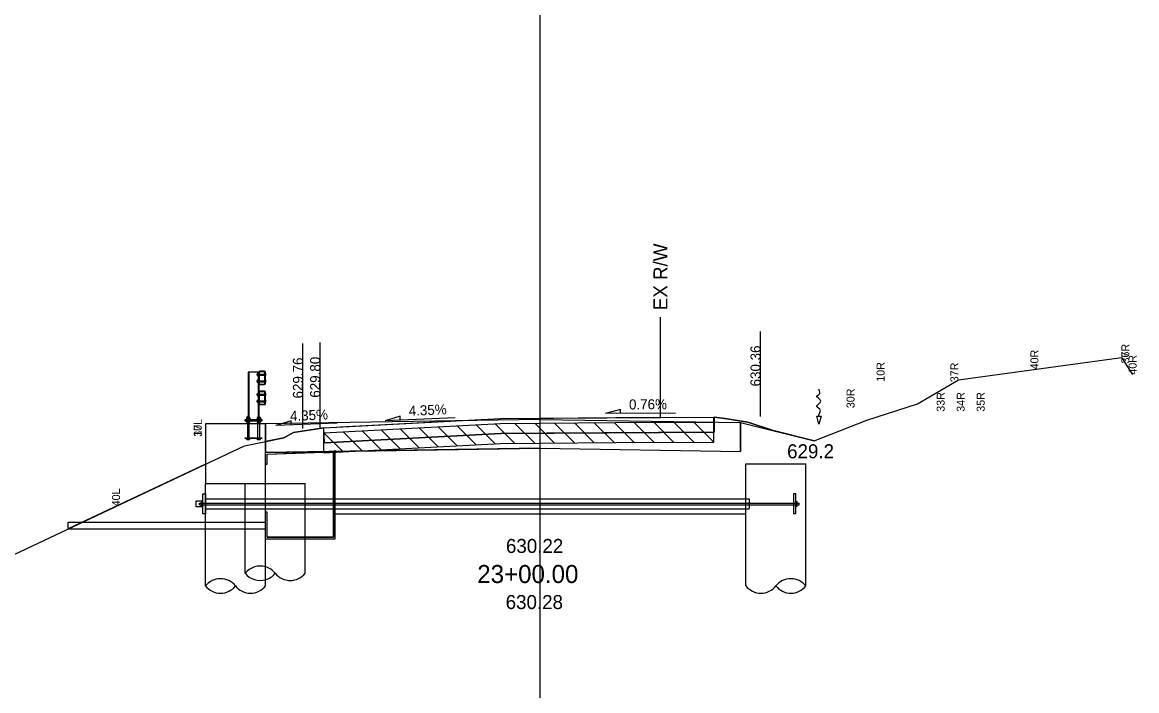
# Model space of a CAD drawing. Extents: x 1866342 to 1870084, y 421982 to 426629.
# Drawn here: x 1866442.2 to 1866497.9, y 422514.3 to 422547.7 of the extents above; entities that cross this region are included whole.
import ezdxf

# ---------------------------------------------------------------- set-up
doc = ezdxf.new("R2010")
doc.units = 0
for name, color, linetype in [('BR_P_Det_Object', 7, 'Continuous'), ('BR_P_Drain_Object', 7, 'Continuous'), ('BR_P_Gen_Hatch', 7, 'Continuous'), ('BR_P_Gen_Porous_Backfill', 7, 'Continuous'), ('BR_P_Sub_Deep_Hidden', 7, 'Continuous'), ('BR_P_Sub_Deep_Object', 7, 'Continuous'), ('BR_P_Sub_Object', 7, 'Continuous'), ('DR_P_Flow_Arrow', 7, 'Continuous'), ('GK_Cells', 7, 'Continuous'), ('RW_X_Fee_RW', 7, 'Continuous'), ('ST_Details', 7, 'Continuous'), ('XS_P_Annotation', 7, 'Continuous'), ('XS_P_Earthwork_Shapes', 7, 'Continuous'), ('XS_P_Finished_Grade', 7, 'Continuous'), ('XS_P_Pavt_Surface', 7, 'Continuous'), ('XS_P_Subgrade', 7, 'Continuous'), ('XS_P_Text_Info', 7, 'Continuous'), ('XS_P_Text_MarkedPoint', 7, 'Continuous'), ('XS_X_Ground_Line', 7, 'Continuous'), ('XS_X_Pavt', 7, 'Continuous')]:
    doc.layers.add(name, color=color, linetype=linetype)

msp = doc.modelspace()

# ---------------------------------------------------------------- linework, layer by layer
at = {"layer": 'BR_P_Det_Object'}
for p, q in [((1866451.264, 422523.135), (1866451.264, 422524.135)), ((1866451.264, 422524.135), (1866451.389, 422524.135)), ((1866451.389, 422524.135), (1866451.389, 422523.135)), ((1866451.389, 422523.885), (1866454.389, 422523.885)), ((1866480.764, 422524.135), (1866480.764, 422523.135)), ((1866480.889, 422524.135), (1866480.764, 422524.135)), ((1866480.889, 422523.135), (1866480.889, 422524.135)), ((1866450.93, 422523.484), (1866450.93, 422523.783)), ((1866450.93, 422523.783), (1866451.264, 422523.783)), ((1866451.264, 422523.484), (1866450.93, 422523.484)), ((1866451.097, 422523.676), (1866481.055, 422523.676)), ((1866451.097, 422523.593), (1866451.097, 422523.676)), ((1866451.097, 422523.593), (1866481.055, 422523.593)), ((1866451.264, 422523.729), (1866451.2, 422523.729)), ((1866451.2, 422523.54), (1866451.2, 422523.729)), ((1866451.264, 422523.54), (1866451.2, 422523.54)), ((1866451.389, 422523.385), (1866454.389, 422523.385)), ((1866480.889, 422523.75), (1866480.952, 422523.75)), ((1866480.889, 422523.52), (1866480.952, 422523.52)), ((1866480.952, 422523.52), (1866480.952, 422523.75)), ((1866481.055, 422523.593), (1866481.055, 422523.676)), ((1866451.389, 422523.135), (1866451.264, 422523.135)), ((1866480.889, 422523.135), (1866480.764, 422523.135))]:
    msp.add_line(p, q, dxfattribs=at)
at = {"layer": 'BR_P_Drain_Object'}
for p, q in [((1866454.389, 422523.885), (1866478.555, 422523.885)), ((1866478.555, 422523.885), (1866478.555, 422523.385)), ((1866454.389, 422523.385), (1866478.555, 422523.385)), ((1866444.524, 422522.718), (1866454.389, 422522.718)), ((1866444.524, 422522.385), (1866444.524, 422522.718)), ((1866444.524, 422522.385), (1866454.389, 422522.385))]:
    msp.add_line(p, q, dxfattribs=at)
at = {"layer": 'BR_P_Gen_Hatch'}
msp.add_lwpolyline([(1866454.389, 422525.617), (1866454.472, 422525.617), (1866454.472, 422526.117), (1866457.789, 422526.24), (1866457.789, 422521.968), (1866454.472, 422521.968), (1866454.472, 422523.218), (1866454.389, 422523.218)], close=True, dxfattribs=at)
at = {"layer": 'BR_P_Gen_Porous_Backfill'}
for p, q in [((1866454.472, 422526.117), (1866457.389, 422526.234)), ((1866454.472, 422525.617), (1866454.472, 422526.117)), ((1866457.789, 422526.24), (1866457.389, 422526.234)), ((1866457.789, 422521.968), (1866457.789, 422526.24)), ((1866454.472, 422525.617), (1866454.389, 422525.617)), ((1866454.472, 422523.218), (1866454.389, 422523.218)), ((1866454.472, 422521.968), (1866454.472, 422523.218)), ((1866454.472, 422521.968), (1866457.789, 422521.968))]:
    msp.add_line(p, q, dxfattribs=at)
at = {"layer": 'BR_P_Sub_Deep_Hidden'}
msp.add_line((1866456.373, 422524.635), (1866454.389, 422524.635), dxfattribs=at)
for points in [[(1866453.373, 422520.171), (1866453.373, 422524.635)], [(1866456.373, 422521.885), (1866456.373, 422524.635)]]:
    msp.add_lwpolyline(points, dxfattribs=at)
for centre, major_axis, start_param, end_param in [((1866454.123, 422519.568), (0.908, 0.32), 0.952163, 2.125879), ((1866454.123, 422520.774), (0.908, -0.32), 4.157306, 5.331022)]:
    msp.add_ellipse(centre, major_axis=major_axis, ratio=0.999997, start_param=start_param, end_param=end_param, dxfattribs=at)
at = {"layer": 'BR_P_Sub_Deep_Object'}
msp.add_line((1866478.389, 422525.635), (1866481.389, 422525.635), dxfattribs=at)
for points in [[(1866478.389, 422519.538), (1866478.389, 422525.635)], [(1866481.389, 422519.538), (1866481.389, 422525.635)], [(1866451.389, 422519.538), (1866451.389, 422524.635)], [(1866454.389, 422519.538), (1866454.389, 422524.635)], [(1866456.373, 422520.171), (1866456.373, 422521.885)]]:
    msp.add_lwpolyline(points, dxfattribs=at)
for centre, major_axis, start_param, end_param in [((1866454.123, 422519.568), (0.908, 0.32), 0.338571, 0.952163), ((1866454.123, 422520.774), (0.908, -0.32), 5.331022, 5.944615), ((1866455.623, 422520.774), (0.908, 0.32), 3.480163, 5.267472), ((1866452.139, 422518.935), (0.908, 0.32), 0.338571, 2.125879), ((1866452.139, 422520.141), (0.908, -0.32), 4.157306, 5.944615), ((1866453.639, 422520.141), (0.908, 0.32), 3.480163, 5.267472), ((1866479.139, 422520.141), (-0.908, 0.32), 1.015713, 2.803022), ((1866480.639, 422518.935), (-0.908, 0.32), 4.157306, 5.944615), ((1866480.639, 422520.141), (-0.908, -0.32), 0.33857, 2.125879)]:
    msp.add_ellipse(centre, major_axis=major_axis, ratio=0.999997, start_param=start_param, end_param=end_param, dxfattribs=at)
at = {"layer": 'BR_P_Sub_Object'}
for p, q in [((1866454.389, 422527.635), (1866451.389, 422527.635)), ((1866451.389, 422527.635), (1866451.389, 422524.635)), ((1866454.389, 422524.635), (1866454.389, 422527.635))]:
    msp.add_line(p, q, dxfattribs=at)
msp.add_lwpolyline([(1866454.389, 422524.635), (1866451.389, 422524.635)], dxfattribs=at)
at = {"layer": 'DR_P_Flow_Arrow'}
for p, q in [((1866482.037, 422527.616), (1866481.93, 422528.016)), ((1866481.93, 422528.016), (1866482.145, 422528.016)), ((1866482.145, 422528.016), (1866482.037, 422527.616))]:
    msp.add_line(p, q, dxfattribs=at)
msp.add_spline([(1866482.038, 422528.016), (1866482.038, 422528.032), (1866482.076, 422528.196), (1866482.112, 422528.301), (1866481.928, 422528.513), (1866482.135, 422528.755), (1866481.928, 422529.035), (1866482.04, 422529.092), (1866482.037, 422529.366)], degree=3, dxfattribs=at)
at = {"layer": 'GK_Cells'}
msp.add_line((1866468.119, 422490.634), (1866468.119, 422611.57), dxfattribs=at)
at = {"layer": 'RW_X_Fee_RW'}
msp.add_line((1866474.119, 422527.954), (1866474.119, 422532.954), dxfattribs=at)
at = {"layer": 'ST_Details'}
for p, q in [((1866453.524, 422530.218), (1866453.524, 422528)), ((1866454.055, 422530.218), (1866453.524, 422530.218)), ((1866453.562, 422530.218), (1866453.562, 422527.993)), ((1866453.971, 422530.119), (1866453.955, 422530.119)), ((1866453.955, 422530.119), (1866453.955, 422530.067)), ((1866453.971, 422530.067), (1866453.955, 422530.067)), ((1866453.971, 422530.126), (1866453.971, 422530.06)), ((1866453.98, 422530.071), (1866454.017, 422530.071)), ((1866454.017, 422530.137), (1866453.981, 422530.137)), ((1866453.981, 422530.115), (1866454.017, 422530.115)), ((1866453.981, 422530.049), (1866454.017, 422530.049)), ((1866454.017, 422530.218), (1866454.017, 422527.993)), ((1866454.017, 422530.049), (1866454.017, 422530.137)), ((1866454.055, 422530.218), (1866454.055, 422528)), ((1866454.055, 422530.208), (1866454.055, 422529.645)), ((1866454.081, 422530.208), (1866454.081, 422529.645)), ((1866454.081, 422530.119), (1866454.363, 422530.119)), ((1866454.081, 422530.067), (1866454.363, 422530.067)), ((1866454.337, 422530.26), (1866454.107, 422530.26)), ((1866454.337, 422530.234), (1866454.107, 422530.234)), ((1866454.363, 422529.645), (1866454.363, 422530.208)), ((1866454.389, 422529.645), (1866454.389, 422530.208)), ((1866453.971, 422529.786), (1866453.955, 422529.786)), ((1866453.955, 422529.786), (1866453.955, 422529.734)), ((1866453.971, 422529.734), (1866453.955, 422529.734)), ((1866453.971, 422529.793), (1866453.971, 422529.726)), ((1866453.98, 422529.738), (1866454.017, 422529.738)), ((1866454.017, 422529.804), (1866453.981, 422529.804)), ((1866453.981, 422529.782), (1866454.017, 422529.782)), ((1866453.981, 422529.715), (1866454.017, 422529.715)), ((1866454.017, 422529.715), (1866454.017, 422529.804)), ((1866454.081, 422529.786), (1866454.363, 422529.786)), ((1866454.081, 422529.734), (1866454.363, 422529.734)), ((1866454.107, 422529.619), (1866454.337, 422529.619)), ((1866454.107, 422529.593), (1866454.337, 422529.593)), ((1866453.971, 422529.119), (1866453.955, 422529.119)), ((1866453.955, 422529.119), (1866453.955, 422529.067)), ((1866453.971, 422529.067), (1866453.955, 422529.067)), ((1866453.971, 422529.126), (1866453.971, 422529.06)), ((1866453.98, 422529.071), (1866454.017, 422529.071)), ((1866454.017, 422529.137), (1866453.981, 422529.137)), ((1866453.981, 422529.115), (1866454.017, 422529.115)), ((1866453.981, 422529.049), (1866454.017, 422529.049)), ((1866454.017, 422529.049), (1866454.017, 422529.137)), ((1866454.055, 422529.228), (1866454.055, 422528.624)), ((1866454.081, 422529.208), (1866454.081, 422528.645)), ((1866454.081, 422529.119), (1866454.363, 422529.119)), ((1866454.081, 422529.067), (1866454.363, 422529.067)), ((1866454.357, 422529.26), (1866454.087, 422529.26)), ((1866454.337, 422529.234), (1866454.107, 422529.234)), ((1866454.363, 422528.645), (1866454.363, 422529.208)), ((1866454.389, 422528.624), (1866454.389, 422529.228)), ((1866453.971, 422528.786), (1866453.955, 422528.786)), ((1866453.955, 422528.786), (1866453.955, 422528.734)), ((1866453.971, 422528.734), (1866453.955, 422528.734)), ((1866453.971, 422528.793), (1866453.971, 422528.726)), ((1866453.98, 422528.738), (1866454.017, 422528.738)), ((1866454.017, 422528.804), (1866453.981, 422528.804)), ((1866453.981, 422528.782), (1866454.017, 422528.782)), ((1866453.981, 422528.715), (1866454.017, 422528.715)), ((1866454.017, 422528.715), (1866454.017, 422528.804)), ((1866454.081, 422528.786), (1866454.363, 422528.786)), ((1866454.081, 422528.734), (1866454.363, 422528.734)), ((1866454.087, 422528.593), (1866454.357, 422528.593)), ((1866454.107, 422528.619), (1866454.337, 422528.619)), ((1866453.441, 422527.868), (1866453.607, 422527.868)), ((1866453.441, 422527.854), (1866453.441, 422527.868)), ((1866453.607, 422527.854), (1866453.441, 422527.854)), ((1866453.446, 422527.935), (1866453.446, 422527.868)), ((1866453.602, 422527.868), (1866453.446, 422527.868)), ((1866453.465, 422527.95), (1866453.582, 422527.95)), ((1866453.482, 422527.989), (1866453.493, 422528)), ((1866453.482, 422527.989), (1866453.566, 422527.989)), ((1866453.482, 422527.989), (1866453.482, 422527.95)), ((1866453.482, 422527.979), (1866453.566, 422527.979)), ((1866453.482, 422527.968), (1866453.566, 422527.968)), ((1866453.482, 422527.958), (1866453.566, 422527.958)), ((1866453.482, 422527.854), (1866453.482, 422527.77)), ((1866453.485, 422527.935), (1866453.485, 422527.868)), ((1866453.555, 422528), (1866453.493, 422528)), ((1866453.555, 422528), (1866453.566, 422527.989)), ((1866453.563, 422527.935), (1866453.563, 422527.868)), ((1866453.566, 422527.95), (1866453.566, 422527.989)), ((1866453.566, 422527.77), (1866453.566, 422527.854)), ((1866453.602, 422527.935), (1866453.602, 422527.868)), ((1866453.607, 422527.868), (1866453.607, 422527.854)), ((1866454.138, 422527.868), (1866453.972, 422527.868)), ((1866453.972, 422527.868), (1866453.972, 422527.854)), ((1866453.972, 422527.854), (1866454.138, 422527.854)), ((1866453.977, 422527.935), (1866453.977, 422527.868)), ((1866453.977, 422527.868), (1866454.133, 422527.868)), ((1866454.114, 422527.95), (1866453.996, 422527.95)), ((1866454.024, 422528), (1866454.013, 422527.989)), ((1866454.097, 422527.989), (1866454.013, 422527.989)), ((1866454.013, 422527.95), (1866454.013, 422527.989)), ((1866454.097, 422527.979), (1866454.013, 422527.979)), ((1866454.097, 422527.968), (1866454.013, 422527.968)), ((1866454.097, 422527.958), (1866454.013, 422527.958)), ((1866454.013, 422527.77), (1866454.013, 422527.854)), ((1866454.016, 422527.935), (1866454.016, 422527.868)), ((1866454.024, 422528), (1866454.086, 422528)), ((1866454.097, 422527.989), (1866454.086, 422528)), ((1866454.094, 422527.935), (1866454.094, 422527.868)), ((1866454.097, 422527.989), (1866454.097, 422527.95)), ((1866454.097, 422527.854), (1866454.097, 422527.77)), ((1866454.133, 422527.935), (1866454.133, 422527.868)), ((1866454.138, 422527.854), (1866454.138, 422527.868)), ((1866453.441, 422527.77), (1866453.607, 422527.77)), ((1866453.441, 422527.756), (1866453.441, 422527.77)), ((1866453.607, 422527.756), (1866453.441, 422527.756)), ((1866453.446, 422527.726), (1866453.446, 422527.756)), ((1866453.465, 422527.71), (1866453.582, 422527.71)), ((1866453.482, 422527.645), (1866453.482, 422527.71)), ((1866453.482, 422527.645), (1866453.482, 422526.927)), ((1866453.485, 422527.726), (1866453.485, 422527.756)), ((1866453.563, 422527.726), (1866453.563, 422527.756)), ((1866453.566, 422527.645), (1866453.566, 422527.71)), ((1866453.566, 422526.927), (1866453.566, 422527.645)), ((1866453.602, 422527.726), (1866453.602, 422527.756)), ((1866453.607, 422527.77), (1866453.607, 422527.756)), ((1866453.972, 422527.77), (1866454.138, 422527.77)), ((1866453.972, 422527.756), (1866453.972, 422527.77)), ((1866454.138, 422527.756), (1866453.972, 422527.756)), ((1866453.977, 422527.726), (1866453.977, 422527.756)), ((1866453.996, 422527.71), (1866454.114, 422527.71)), ((1866454.013, 422527.645), (1866454.013, 422527.71)), ((1866454.013, 422526.927), (1866454.013, 422527.645)), ((1866454.016, 422527.726), (1866454.016, 422527.756)), ((1866454.094, 422527.726), (1866454.094, 422527.756)), ((1866454.097, 422527.645), (1866454.097, 422527.71)), ((1866454.097, 422527.645), (1866454.097, 422526.927)), ((1866454.133, 422527.726), (1866454.133, 422527.756)), ((1866454.138, 422527.77), (1866454.138, 422527.756)), ((1866453.446, 422526.86), (1866453.446, 422526.895)), ((1866453.465, 422526.845), (1866453.582, 422526.845)), ((1866453.485, 422526.86), (1866453.485, 422526.895)), ((1866453.563, 422526.86), (1866453.563, 422526.895)), ((1866453.602, 422526.86), (1866453.602, 422526.895)), ((1866453.977, 422526.86), (1866453.977, 422526.895)), ((1866454.114, 422526.845), (1866453.996, 422526.845)), ((1866454.016, 422526.86), (1866454.016, 422526.895)), ((1866454.094, 422526.86), (1866454.094, 422526.895)), ((1866454.133, 422526.86), (1866454.133, 422526.895))]:
    msp.add_line(p, q, dxfattribs=at)
for points in [[(1866453.373, 422527.854), (1866454.206, 422527.854), (1866454.206, 422527.77), (1866453.373, 422527.77)], [(1866453.373, 422526.927), (1866454.206, 422526.927), (1866454.206, 422526.895), (1866453.373, 422526.895)]]:
    msp.add_lwpolyline(points, close=True, dxfattribs=at)
for centre, radius, start, end in [((1866454.107, 422530.208), 0.0521, 90, 180), ((1866454.107, 422530.208), 0.026, 90, 180), ((1866454.337, 422530.208), 0.0521, 0, 90), ((1866454.337, 422530.208), 0.026, 0, 90), ((1866454.361, 422530.093), 0.0558, 300, 60), ((1866454.107, 422529.645), 0.0521, 180, 270), ((1866454.107, 422529.645), 0.026, 180, 270), ((1866454.337, 422529.645), 0.0521, 270, 0), ((1866454.337, 422529.645), 0.026, 270, 0), ((1866454.361, 422529.76), 0.0558, 300, 60), ((1866454.087, 422529.228), 0.0312, 90, 180), ((1866454.107, 422529.208), 0.026, 90, 180), ((1866454.337, 422529.208), 0.026, 0, 90), ((1866454.357, 422529.228), 0.0312, 0, 90), ((1866454.361, 422529.093), 0.0558, 300, 60), ((1866454.087, 422528.624), 0.0312, 180, 270), ((1866454.107, 422528.645), 0.026, 180, 270), ((1866454.337, 422528.645), 0.026, 270, 0), ((1866454.357, 422528.624), 0.0312, 270, 0), ((1866454.361, 422528.76), 0.0558, 300, 60)]:
    msp.add_arc(centre, radius, start, end, dxfattribs=at)
for centre, major_axis, ratio, start_param, end_param in [((1866453.981, 422530.126), (0, -0.0111), 0.939759, 3.141593, 6.283185), ((1866453.981, 422530.093), (0, -0.0222), 0.469173, 3.141593, 6.283185), ((1866453.981, 422530.06), (0, 0.0111), 0.939759, 0, 3.141593), ((1866453.981, 422529.793), (0, -0.0111), 0.939759, 3.141593, 6.283185), ((1866453.981, 422529.76), (0, -0.0222), 0.469173, 3.141593, 6.283185), ((1866453.981, 422529.726), (0, 0.0111), 0.939759, 0, 3.141593), ((1866453.981, 422529.126), (0, -0.0111), 0.939759, 3.141593, 6.283185), ((1866453.981, 422529.093), (0, -0.0222), 0.469173, 3.141593, 6.283185), ((1866453.981, 422529.06), (0, 0.0111), 0.939759, 0, 3.141593), ((1866453.981, 422528.793), (0, -0.0111), 0.939759, 3.141593, 6.283185), ((1866453.981, 422528.76), (0, -0.0222), 0.469173, 3.141593, 6.283185), ((1866453.981, 422528.726), (0, 0.0111), 0.939759, 0, 3.141593), ((1866453.465, 422527.935), (0.0195, 0), 0.798056, 0, 3.141593), ((1866453.524, 422527.935), (0.0391, 0), 0.399304, 0, 3.141593), ((1866453.582, 422527.935), (0.0195, 0), 0.798056, 0, 3.141593), ((1866453.996, 422527.935), (-0.0195, 0), 0.798056, 3.141593, 6.283185), ((1866454.055, 422527.935), (-0.0391, 0), 0.399304, 3.141593, 6.283185), ((1866454.114, 422527.935), (-0.0195, 0), 0.798056, 3.141593, 6.283185), ((1866453.465, 422527.726), (0.0195, 0), 0.798056, 3.141593, 6.283185), ((1866453.524, 422527.726), (0.0391, 0), 0.399304, 3.141593, 6.283185), ((1866453.582, 422527.726), (0.0195, 0), 0.798056, 3.141593, 6.283185), ((1866453.996, 422527.726), (0.0195, 0), 0.798056, 3.141593, 6.283185), ((1866454.055, 422527.726), (0.0391, 0), 0.399304, 3.141593, 6.283185), ((1866454.114, 422527.726), (0.0195, 0), 0.798056, 3.141593, 6.283185), ((1866453.465, 422526.86), (0.0195, 0), 0.798056, 3.141593, 6.283185), ((1866453.524, 422526.86), (0.0391, 0), 0.399304, 3.141593, 6.283185), ((1866453.582, 422526.86), (0.0195, 0), 0.798056, 3.141593, 6.283185), ((1866453.996, 422526.86), (-0.0195, 0), 0.798056, 0, 3.141593), ((1866454.055, 422526.86), (-0.0391, 0), 0.399304, 0, 3.141593), ((1866454.114, 422526.86), (-0.0195, 0), 0.798056, 0, 3.141593)]:
    msp.add_ellipse(centre, major_axis=major_axis, ratio=ratio, start_param=start_param, end_param=end_param, dxfattribs=at)
at = {"layer": 'XS_P_Annotation'}
for q in [(1866454.389, 422527.635), (1866478.119, 422527.694)]:
    msp.add_line((1866468.119, 422527.854), q, dxfattribs=at)
at = {"layer": 'XS_P_Earthwork_Shapes'}
for p, q in [((1866478.119, 422526.257), (1866478.119, 422527.694)), ((1866478.119, 422527.694), (1866481.808, 422526.785)), ((1866454.389, 422526.75), (1866454.389, 422526.197)), ((1866468.119, 422526.417), (1866478.119, 422526.257))]:
    msp.add_line(p, q, dxfattribs=at)
for points in [[(1866481.808, 422526.785), (1866479.751, 422527.306), (1866478.479, 422527.714), (1866477.333, 422527.896), (1866476.8, 422527.964), (1866476.804, 422527.214), (1866468.445, 422527.161), (1866466.145, 422527.147), (1866457.345, 422526.686), (1866457.306, 422527.435), (1866455.786, 422527.192), (1866455.306, 422526.938), (1866454.389, 422526.75)], [(1866457.306, 422527.435), (1866466.123, 422527.897), (1866476.8, 422527.964)], [(1866457.345, 422526.686), (1866466.145, 422527.147), (1866476.804, 422527.214)], [(1866454.389, 422526.197), (1866457.873, 422526.253), (1866468.119, 422526.417)]]:
    msp.add_lwpolyline(points, dxfattribs=at)
at = {"layer": 'XS_P_Finished_Grade'}
for p, q in [((1866478.119, 422527.694), (1866481.808, 422526.785)), ((1866451.389, 422525.617), (1866444.524, 422522.385))]:
    msp.add_line(p, q, dxfattribs=at)
at = {"layer": 'XS_P_Pavt_Surface'}
for p, q in [((1866458.119, 422527.478), (1866466.123, 422527.897)), ((1866466.123, 422527.897), (1866476.789, 422527.964))]:
    msp.add_line(p, q, dxfattribs=at)
at = {"layer": 'XS_P_Subgrade'}
for p, q in [((1866454.389, 422527.635), (1866454.389, 422526.197)), ((1866478.119, 422527.694), (1866478.119, 422526.257)), ((1866468.119, 422526.417), (1866454.389, 422526.197)), ((1866457.873, 422521.885), (1866457.873, 422526.317)), ((1866468.119, 422526.417), (1866478.119, 422526.257)), ((1866457.873, 422523.135), (1866478.389, 422523.135)), ((1866454.389, 422521.885), (1866457.873, 422521.885))]:
    msp.add_line(p, q, dxfattribs=at)
at = {"layer": 'XS_P_Text_Info'}
for p, q in [((1866479.119, 422527.998), (1866479.119, 422532.248)), ((1866457.119, 422527.435), (1866457.119, 422531.685)), ((1866456.259, 422527.397), (1866456.259, 422531.647)), ((1866472.119, 422528.344), (1866471.369, 422528.139)), ((1866472.119, 422528.144), (1866472.119, 422528.344)), ((1866455.677, 422527.773), (1866454.91, 422527.54)), ((1866455.677, 422527.573), (1866455.677, 422527.773)), ((1866461.119, 422528.009), (1866460.369, 422527.776)), ((1866463.869, 422527.929), (1866460.369, 422527.776)), ((1866461.119, 422527.809), (1866461.119, 422528.009)), ((1866474.869, 422528.165), (1866471.369, 422528.139)), ((1866457.975, 422527.671), (1866454.91, 422527.54))]:
    msp.add_line(p, q, dxfattribs=at)
at = {"layer": 'XS_X_Ground_Line'}
msp.add_line((1866451.389, 422527.635), (1866451.389, 422525.635), dxfattribs=at)
msp.add_lwpolyline([(1866436.211, 422518.469), (1866453.333, 422526.533), (1866455.306, 422526.938), (1866455.786, 422527.192), (1866457.306, 422527.435), (1866461.074, 422527.628), (1866466.123, 422527.897), (1866468.119, 422527.914), (1866471.899, 422527.946), (1866476.8, 422527.964), (1866477.333, 422527.896), (1866478.479, 422527.714), (1866479.751, 422527.306), (1866481.808, 422526.785), (1866484.432, 422527.82), (1866486.961, 422528.626), (1866489.003, 422529.824), (1866497.149, 422530.946), (1866497.709, 422530.086)], dxfattribs=at)
at = {"layer": 'XS_X_Pavt'}
for p, q in [((1866476.789, 422527.714), (1866476.789, 422527.964)), ((1866457.306, 422527.185), (1866457.306, 422527.435)), ((1866457.306, 422527.185), (1866461.074, 422527.378)), ((1866459.214, 422526.283), (1866458.262, 422527.234)), ((1866460.165, 422526.332), (1866459.214, 422527.283)), ((1866461.117, 422526.381), (1866460.165, 422527.332)), ((1866461.074, 422527.378), (1866466.123, 422527.647)), ((1866462.067, 422526.43), (1866461.117, 422527.381)), ((1866463.017, 422526.481), (1866462.067, 422527.43)), ((1866463.968, 422526.53), (1866463.017, 422527.481)), ((1866464.92, 422526.578), (1866463.968, 422527.53)), ((1866465.877, 422526.622), (1866464.92, 422527.578)), ((1866466.846, 422526.653), (1866465.877, 422527.622)), ((1866466.123, 422527.647), (1866468.119, 422527.664)), ((1866467.838, 422526.661), (1866466.846, 422527.653)), ((1866468.83, 422526.67), (1866467.838, 422527.661)), ((1866468.119, 422527.664), (1866471.899, 422527.696)), ((1866469.822, 422526.678), (1866468.83, 422527.67)), ((1866470.815, 422526.686), (1866469.822, 422527.678)), ((1866471.807, 422526.694), (1866470.815, 422527.686)), ((1866472.802, 422526.699), (1866471.807, 422527.694)), ((1866471.899, 422527.696), (1866476.789, 422527.714)), ((1866473.799, 422526.703), (1866472.802, 422527.699)), ((1866474.796, 422526.707), (1866473.799, 422527.703)), ((1866475.792, 422526.711), (1866474.796, 422527.707)), ((1866476.789, 422526.714), (1866475.792, 422527.711)), ((1866476.789, 422526.714), (1866476.789, 422527.714)), ((1866457.306, 422526.185), (1866457.306, 422527.185)), ((1866458.262, 422526.234), (1866457.345, 422527.151)), ((1866466.123, 422526.647), (1866468.119, 422526.664)), ((1866468.119, 422526.664), (1866471.899, 422526.696)), ((1866471.899, 422526.696), (1866476.789, 422526.714)), ((1866457.306, 422526.185), (1866461.074, 422526.378)), ((1866461.074, 422526.378), (1866466.123, 422526.647))]:
    msp.add_line(p, q, dxfattribs=at)

# ---------------------------------------------------------------- texts
at = {"layer": 'RW_X_Fee_RW'}
msp.add_text('EX R/W', height=0.7, rotation=90, dxfattribs=at).set_placement((1866474.469, 422533.304))
at = {"layer": 'XS_P_Annotation'}
for s, height, p in [('629.2', 0.7, (1866480.449, 422525.911)), ('630.22', 0.7, (1866466.402, 422521.184)), ('23+00.00', 0.9, (1866464.969, 422519.684)), ('630.28', 0.7, (1866466.388, 422518.384))]:
    msp.add_text(s, height=height, dxfattribs=at).set_placement(p)
at = {"layer": 'XS_P_Text_Info'}
for s, rotation, p in [('630.36', 90, (1866479.119, 422529.498)), ('629.76', 90, (1866456.259, 422528.897)), ('629.80', 90, (1866457.119, 422528.935)), ('4.35%', 2.4932, (1866455.625, 422527.77)), ('4.35%', 2.4932, (1866461.555, 422528.028)), ('0.76%', 0.4378, (1866472.551, 422528.348))]:
    msp.add_text(s, height=0.5, rotation=rotation, dxfattribs=at).set_placement(p)
at = {"layer": 'XS_P_Text_MarkedPoint'}
for s, p in [('40R', (1866493.005, 422530.348)), ('36R', (1866497.547, 422530.642)), ('37R', (1866497.547, 422530.642)), ('10R', (1866485.319, 422529.733)), ('37R', (1866489.005, 422529.708)), ('40R', (1866497.909, 422530.086)), ('30R', (1866483.819, 422528.411)), ('33R', (1866488.319, 422528.233)), ('34R', (1866489.319, 422528.233)), ('35R', (1866490.319, 422528.233)), ('10L', (1866451.207, 422526.986)), ('37L', (1866451.207, 422526.986)), ('40L', (1866447.12, 422523.513))]:
    msp.add_text(s, height=0.4, rotation=90, dxfattribs=at).set_placement(p)

doc.saveas('drawing.dxf')
